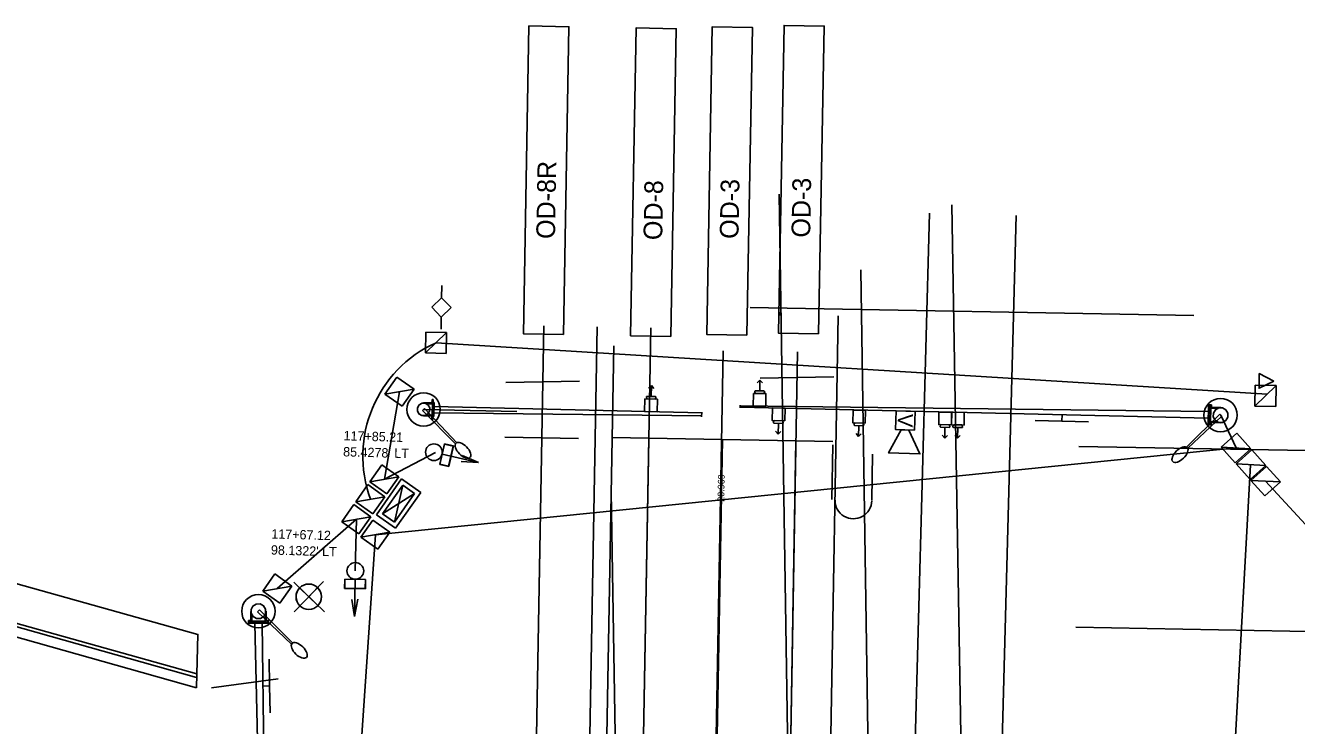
# Model space of a CAD drawing. Extents: x 925524 to 926006, y 853415 to 857998.
# Drawn here: x 925686 to 925876.1, y 853632 to 853736.7 of the extents above; entities that cross this region are included whole.
import ezdxf

# ---------------------------------------------------------------- set-up
doc = ezdxf.new("R2010")
doc.units = 0
for name, color, linetype in [('ConduitDB', 7, 'Continuous'), ('ConduitOT', 7, 'Continuous'), ('ConstLines', 7, 'Continuous'), ('ControllerB', 7, 'Continuous'), ('Core', 7, 'Continuous'), ('DetectorVeh', 7, 'Continuous'), ('EasePerpLine', 7, 'Continuous'), ('Luminaire', 7, 'Continuous'), ('Miscellaneous0', 7, 'Continuous'), ('NonPlottingEle_dp', 7, 'Continuous'), ('OverheadStr', 7, 'Continuous'), ('Pedestal', 7, 'Continuous'), ('PedHead', 7, 'Continuous'), ('PoleFound', 7, 'Continuous'), ('PullBox', 7, 'Continuous'), ('ScratchEle2_dp', 7, 'Continuous'), ('ScratchEle_dp', 7, 'Continuous'), ('SidewalkBack', 7, 'Continuous'), ('SignalHead', 7, 'Continuous'), ('SignPanel', 7, 'Continuous'), ('TextMinor', 7, 'Continuous'), ('TransformerAer', 7, 'Continuous')]:
    doc.layers.add(name, color=color, linetype=linetype)

msp = doc.modelspace()

# ---------------------------------------------------------------- linework, layer by layer
at = {"layer": 'ConduitDB'}
for p, q in [((925747.41, 853689.24), (925871.68, 853681.57)), ((925738.35, 853660.55), (925867.01, 853673.51)), ((925869.15, 853671.01), (925859.35, 853493.47)), ((925738.35, 853660.55), (925727.58, 853500.34))]:
    msp.add_line(p, q, dxfattribs=at)
at = {"layer": 'ConduitOT'}
for p, q in [((925739.7, 853668.83), (925741.95, 853681.92)), ((925739.7, 853668.83), (925747.31, 853672.84)), ((925871.43, 853668.55), (925884.05, 853654.81)), ((925723.67, 853652.5), (925735.5, 853662.86)), ((925735.5, 853662.86), (925735.35, 853655.13))]:
    msp.add_line(p, q, dxfattribs=at)
msp.add_lwpolyline([(925867.01, 853673.51), (925864.75, 853678.42)], dxfattribs=at)
msp.add_arc((925755.1, 853672.27), 18.63, 114.3621, 200.1371, dxfattribs=at)
at = {"layer": 'ConstLines'}
for p, q in [((925821.17, 853708.61), (925814.44, 853457.33)), ((925834.16, 853708.27), (925827.43, 853456.98)), ((925807.55, 853693.24), (925803.33, 853457.33)), ((925773.58, 853666.98), (925777.16, 853456.64))]:
    msp.add_line(p, q, dxfattribs=at)
at = {"layer": 'ControllerB'}
for p, q in [((925738.5, 853663.51), (925742.27, 853668.88)), ((925739.41, 853663.67), (925742.43, 853667.96)), ((925741.2, 853662.41), (925742.43, 853667.96)), ((925742.27, 853668.88), (925745.14, 853666.86)), ((925742.43, 853667.96), (925744.22, 853666.7)), ((925744.22, 853666.7), (925739.41, 853663.67)), ((925744.22, 853666.7), (925741.2, 853662.41)), ((925745.14, 853666.86), (925741.36, 853661.5)), ((925741.2, 853662.41), (925739.41, 853663.67)), ((925741.36, 853661.5), (925738.5, 853663.51))]:
    msp.add_line(p, q, dxfattribs=at)
at = {"layer": 'Core'}
for p, q in [((925726.14, 853653.44), (925730.73, 853649.01)), ((925726.22, 853649.03), (925730.6, 853653.56))]:
    msp.add_line(p, q, dxfattribs=at)
for points in [[(925727.02, 853652.59), (925728.39, 853651.27), (925727.06, 853649.9)], [(925729.71, 853652.64), (925728.39, 853651.27), (925729.76, 853649.95)]]:
    msp.add_lwpolyline(points, dxfattribs=at)
msp.add_circle((925728.39, 853651.27), 1.9, dxfattribs=at)
for start, end in [(135.9741, 225.9741), (315.9741, 45.9741)]:
    msp.add_arc((925728.39, 853651.27), 1.9, start, end, dxfattribs=at)
at = {"layer": 'DetectorVeh'}
msp.add_line((925816.94, 853676.22), (925818.11, 853676.18), dxfattribs=at)
msp.add_lwpolyline([(925818.93, 853676.16), (925819.02, 853678.97), (925816.21, 853679.06), (925816.12, 853676.25)], close=True, dxfattribs=at)
msp.add_lwpolyline([(925818.11, 853676.18), (925819.75, 853672.61), (925815.06, 853672.77), (925816.94, 853676.22)], dxfattribs=at)
at = {"layer": 'Luminaire'}
for p, q in [((925745.7, 853679.41), (925745.4, 853679.13)), ((925750.33, 853674.13), (925745.4, 853679.13)), ((925750.51, 853674.3), (925745.7, 853679.41)), ((925859.61, 853673.64), (925864.61, 853678.57)), ((925859.78, 853673.46), (925864.89, 853678.27)), ((925864.61, 853678.57), (925864.89, 853678.27)), ((925721, 853649.3), (925720.71, 853649)), ((925725.82, 853644.18), (925720.71, 853649)), ((925725.99, 853644.36), (925721, 853649.3))]:
    msp.add_line(p, q, dxfattribs=at)
for centre, major_axis in [((925751.45, 853673.15), (1.04, -1.08)), ((925858.63, 853672.52), (-1.08, -1.04)), ((925726.97, 853643.25), (1.08, -1.04))]:
    msp.add_ellipse(centre, major_axis=major_axis, ratio=0.5, dxfattribs=at)
at = {"layer": 'Miscellaneous0'}
for p, q in [((925661.93, 853659.63), (925711.79, 853645.62)), ((925662.19, 853653.12), (925711.63, 853639.23)), ((925662.27, 853653.61), (925711.64, 853639.75)), ((925661.96, 853651.62), (925711.59, 853637.68))]:
    msp.add_line(p, q, dxfattribs=at)
at = {"layer": 'NonPlottingEle_dp'}
for p, q in [((925768.72, 853674.91), (925757.72, 853675.11)), ((925773.72, 853675.05), (925784.72, 853674.85)), ((925763.22, 853675.01), (925759.78, 853483.16)), ((925779.22, 853674.95), (925775.92, 853490.92)), ((925784.72, 853674.85), (925795.72, 853674.66)), ((925790.22, 853674.76), (925786.81, 853484.28)), ((925795.72, 853674.66), (925806.72, 853674.46)), ((925801.22, 853674.56), (925797.82, 853484.67)), ((925806.71, 853674), (925806.56, 853665.83)), ((925928.9, 853672.19), (925843.53, 853673.72)), ((925812.68, 853672.56), (925812.56, 853665.73)), ((925928.42, 853645.19), (925843.05, 853646.72))]:
    msp.add_line(p, q, dxfattribs=at)
msp.add_arc((925809.81, 853665.68), 2.75, 178.9741, 358.9741, dxfattribs=at)
at = {"layer": 'OverheadStr'}
for p, q in [((925746.81, 853680.08), (925746.82, 853680.75)), ((925746.82, 853680.75), (925746.99, 853680.74)), ((925746.94, 853677.75), (925746.99, 853680.74)), ((925745.56, 853680.25), (925746.81, 853680.23)), ((925745.56, 853680.25), (925745.56, 853680.19)), ((925745.56, 853680.19), (925746.81, 853680.16)), ((925745.95, 853680.1), (925746.89, 853680.08)), ((925746.86, 853678.41), (925746.89, 853680.08)), ((925746.94, 853678.2), (925746.98, 853680.29)), ((925746.98, 853680.29), (925747.15, 853680.28)), ((925747.11, 853678.2), (925747.15, 853680.28)), ((925747.14, 853679.7), (925787.13, 853678.75)), ((925787.13, 853678.88), (925787.12, 853678.18)), ((925792.89, 853679.49), (925792.9, 853679.92)), ((925862.89, 853678.95), (925792.89, 853679.8)), ((925862.87, 853677.95), (925792.89, 853679.62)), ((925862.91, 853679.95), (925862.86, 853676.95)), ((925863.14, 853679.95), (925862.91, 853679.95)), ((925863.14, 853679.95), (925863.08, 853676.95)), ((925863.14, 853679.95), (925863.08, 853676.95)), ((925863.35, 853679.95), (925863.14, 853679.95)), ((925863.23, 853679.45), (925863.2, 853677.45)), ((925864.28, 853679.43), (925863.23, 853679.45)), ((925863.35, 853679.95), (925863.34, 853679.45)), ((925864.71, 853679.57), (925863.34, 853679.59)), ((925864.71, 853679.5), (925863.34, 853679.53)), ((925864.71, 853679.57), (925864.71, 853679.5)), ((925745.53, 853678.35), (925746.78, 853678.33)), ((925745.53, 853678.29), (925745.53, 853678.35)), ((925745.53, 853678.29), (925746.78, 853678.27)), ((925745.92, 853678.43), (925746.86, 853678.41)), ((925746.77, 853677.75), (925746.78, 853678.41)), ((925746.77, 853677.75), (925746.94, 853677.75)), ((925746.94, 853678.2), (925747.11, 853678.2)), ((925747.12, 853678.78), (925787.12, 853678.3)), ((925863.08, 853676.95), (925862.86, 853676.95)), ((925863.29, 853676.95), (925863.08, 853676.95)), ((925864.24, 853677.43), (925863.2, 853677.45)), ((925863.3, 853677.45), (925863.29, 853676.95)), ((925864.67, 853677.34), (925863.3, 853677.36)), ((925864.67, 853677.28), (925863.3, 853677.3)), ((925864.67, 853677.28), (925864.67, 853677.34)), ((925719.71, 853649.09), (925719.74, 853647.72)), ((925719.71, 853649.09), (925719.78, 853649.09)), ((925719.78, 853649.09), (925719.8, 853647.72)), ((925719.87, 853648.66), (925719.88, 853647.61)), ((925721.87, 853648.69), (925721.88, 853647.65)), ((925721.94, 853649.13), (925721.97, 853647.75)), ((925722.01, 853649.13), (925721.94, 853649.13)), ((925722.01, 853649.13), (925722.03, 853647.75)), ((925719.38, 853647.71), (925719.88, 853647.72)), ((925719.38, 853647.71), (925719.39, 853647.5)), ((925719.39, 853647.5), (925722.39, 853647.55)), ((925719.39, 853647.5), (925722.39, 853647.55)), ((925719.39, 853647.5), (925719.39, 853647.27)), ((925719.39, 853647.27), (925722.39, 853647.32)), ((925719.88, 853647.61), (925721.88, 853647.65)), ((925720.35, 853647.29), (925722.13, 853569.31)), ((925721.43, 853647.31), (925722.3, 853569.31)), ((925721.88, 853647.75), (925722.38, 853647.76)), ((925722.38, 853647.76), (925722.39, 853647.55)), ((925722.39, 853647.55), (925722.39, 853647.32))]:
    msp.add_line(p, q, dxfattribs=at)
for points in [[(925746.47, 853679.5), (925746.46, 853679.01), (925746.21, 853678.59), (925745.78, 853678.35), (925745.28, 853678.36), (925744.86, 853678.61), (925744.63, 853679.04), (925744.63, 853679.53), (925744.89, 853679.95), (925745.32, 853680.19), (925745.81, 853680.18), (925746.23, 853679.93)], [(925863.62, 853678.73), (925863.61, 853678.15), (925863.89, 853677.64), (925864.38, 853677.34), (925864.97, 853677.33), (925865.47, 853677.61), (925865.77, 853678.11), (925865.78, 853678.69), (925865.5, 853679.2), (925865, 853679.5), (925864.42, 853679.51), (925863.92, 853679.23)], [(925720.59, 853648.02), (925721.17, 853648.03), (925721.67, 853648.33), (925721.95, 853648.84), (925721.94, 853649.42), (925721.64, 853649.92), (925721.13, 853650.2), (925720.55, 853650.19), (925720.05, 853649.89), (925719.77, 853649.38), (925719.78, 853648.8), (925720.08, 853648.3)]]:
    msp.add_lwpolyline(points, close=True, dxfattribs=at)
at = {"layer": 'Pedestal'}
for p, q in [((925748.24, 853695.97), (925746.77, 853694.55)), ((925748.24, 853695.97), (925748.28, 853697.8)), ((925749.67, 853694.5), (925748.24, 853695.97)), ((925746.77, 853694.55), (925748.19, 853693.08)), ((925748.19, 853693.08), (925749.67, 853694.5)), ((925748.16, 853691.25), (925748.19, 853693.08))]:
    msp.add_line(p, q, dxfattribs=at)
at = {"layer": 'PedHead'}
for p, q in [((925748.67, 853674.11), (925747.98, 853671.06)), ((925747.98, 853671.1), (925748.66, 853674.07)), ((925748.66, 853674.07), (925749.97, 853673.78)), ((925750.01, 853673.81), (925748.67, 853674.11)), ((925749.97, 853673.78), (925749.29, 853670.8)), ((925749.32, 853670.76), (925750.01, 853673.81)), ((925748.32, 853672.59), (925753.76, 853671.35)), ((925753.76, 853671.35), (925751.19, 853671.48)), ((925753.76, 853671.35), (925751.32, 853672.37)), ((925749.29, 853670.8), (925747.98, 853671.1)), ((925747.98, 853671.06), (925749.32, 853670.76)), ((925733.76, 853653.91), (925733.74, 853652.53)), ((925733.74, 853652.53), (925736.86, 853652.48)), ((925736.89, 853653.85), (925733.76, 853653.91)), ((925733.78, 853652.57), (925733.8, 853653.91)), ((925736.83, 853652.51), (925733.78, 853652.57)), ((925733.8, 853653.91), (925736.85, 853653.85)), ((925735.33, 853653.88), (925735.23, 853648.31)), ((925736.85, 853653.85), (925736.83, 853652.51)), ((925736.86, 853652.48), (925736.89, 853653.85)), ((925735.23, 853648.31), (925734.83, 853650.85)), ((925735.23, 853648.31), (925735.73, 853650.9))]:
    msp.add_line(p, q, dxfattribs=at)
for centre in [(925747.1, 853672.87), (925735.35, 853655.13)]:
    msp.add_circle(centre, 1.25, dxfattribs=at)
at = {"layer": 'PoleFound'}
for centre in [(925745.55, 853679.27), (925864.69, 853678.42), (925720.86, 853649.11)]:
    msp.add_circle(centre, 2.5, dxfattribs=at)
at = {"layer": 'PullBox'}
for p, q in [((925745.82, 853687.71), (925745.88, 853690.83)), ((925745.82, 853687.71), (925749, 853690.77)), ((925745.88, 853690.83), (925749, 853690.77)), ((925749, 853690.77), (925748.94, 853687.65)), ((925748.94, 853687.65), (925745.82, 853687.71)), ((925739.77, 853681.54), (925741.57, 853684.09)), ((925741.57, 853684.09), (925744.13, 853682.29)), ((925869.81, 853679.77), (925869.87, 853682.9)), ((925869.81, 853679.77), (925872.99, 853682.84)), ((925869.87, 853682.9), (925872.99, 853682.84)), ((925872.99, 853682.84), (925872.94, 853679.72)), ((925739.77, 853681.54), (925744.13, 853682.29)), ((925742.33, 853679.74), (925739.77, 853681.54)), ((925744.13, 853682.29), (925742.33, 853679.74)), ((925872.94, 853679.72), (925869.81, 853679.77)), ((925864.8, 853673.63), (925867.13, 853675.72)), ((925867.13, 853675.72), (925869.21, 853673.39)), ((925866.89, 853671.3), (925864.8, 853673.63)), ((925864.8, 853673.63), (925869.21, 853673.39)), ((925869.21, 853673.39), (925866.89, 853671.3)), ((925867.04, 853671.12), (925869.37, 853673.21)), ((925869.37, 853673.21), (925871.45, 853670.88)), ((925737.52, 853668.45), (925739.32, 853671.01)), ((925739.32, 853671.01), (925741.87, 853669.21)), ((925869.12, 853668.79), (925867.04, 853671.12)), ((925867.04, 853671.12), (925871.45, 853670.88)), ((925871.45, 853670.88), (925869.12, 853668.79)), ((925869.23, 853668.67), (925871.56, 853670.76)), ((925871.56, 853670.76), (925873.64, 853668.43)), ((925735.43, 853665.47), (925737.22, 853668.03)), ((925737.22, 853668.03), (925739.78, 853666.23)), ((925737.52, 853668.45), (925741.87, 853669.21)), ((925740.07, 853666.65), (925737.52, 853668.45)), ((925741.87, 853669.21), (925740.07, 853666.65)), ((925871.31, 853666.34), (925869.23, 853668.67)), ((925869.23, 853668.67), (925873.64, 853668.43)), ((925873.64, 853668.43), (925871.31, 853666.34)), ((925735.43, 853665.47), (925739.78, 853666.23)), ((925739.78, 853666.23), (925737.98, 853663.68)), ((925733.32, 853662.48), (925735.12, 853665.04)), ((925735.12, 853665.04), (925737.67, 853663.24)), ((925737.98, 853663.68), (925735.43, 853665.47)), ((925733.32, 853662.48), (925737.67, 853663.24)), ((925735.88, 853660.68), (925733.32, 853662.48)), ((925737.67, 853663.24), (925735.88, 853660.68)), ((925736.17, 853660.17), (925737.97, 853662.73)), ((925737.97, 853662.73), (925740.53, 853660.93)), ((925736.17, 853660.17), (925740.53, 853660.93)), ((925738.73, 853658.38), (925736.17, 853660.17)), ((925740.53, 853660.93), (925738.73, 853658.38)), ((925721.5, 853652.12), (925723.3, 853654.68)), ((925723.3, 853654.68), (925725.85, 853652.88)), ((925721.5, 853652.12), (925725.85, 853652.88)), ((925725.85, 853652.88), (925724.05, 853650.32)), ((925724.05, 853650.32), (925721.5, 853652.12))]:
    msp.add_line(p, q, dxfattribs=at)
at = {"layer": 'ScratchEle2_dp'}
for p, q in [((925798.69, 853711.44), (925803.07, 853432.2)), ((925829.04, 853446.57), (925824.52, 853709.82)), ((925815.37, 853415.34), (925810.9, 853700.12)), ((925763.52, 853691.77), (925759.97, 853493.66)), ((925771.52, 853691.62), (925767.97, 853493.51)), ((925779.52, 853691.48), (925775.97, 853493.37)), ((925773.97, 853688.76), (925770.55, 853498.1)), ((925790.32, 853688.01), (925786.74, 853488.27)), ((925801.46, 853687.88), (925797.66, 853476.1)), ((925757.87, 853683.31), (925768.87, 853683.49)), ((925806.89, 853684.14), (925795.88, 853683.95)), ((925745.55, 853679.27), (925759.51, 853678.94)), ((925713.85, 853637.68), (925723.82, 853639.03))]:
    msp.add_line(p, q, dxfattribs=at)
at = {"layer": 'ScratchEle_dp'}
for p, q in [((925794.37, 853694.48), (925860.69, 853693.3)), ((925798.93, 853693.32), (925798.95, 853694.4))]:
    msp.add_line(p, q, dxfattribs=at)
at = {"layer": 'SidewalkBack'}
msp.add_line((925711.59, 853637.68), (925711.81, 853645.68), dxfattribs=at)
at = {"layer": 'SignalHead'}
for p, q in [((925779.2, 853682.43), (925779.6, 853682.82)), ((925779.57, 853681.21), (925779.6, 853682.82)), ((925779.99, 853682.41), (925779.6, 853682.82)), ((925795.43, 853683.25), (925795.83, 853683.64)), ((925795.8, 853682.04), (925795.83, 853683.64)), ((925796.22, 853683.24), (925795.83, 853683.64)), ((925780.19, 853681.2), (925778.96, 853681.22)), ((925796.42, 853682.03), (925795.19, 853682.05)), ((925797.98, 853677.21), (925799.2, 853677.18)), ((925798.59, 853677.2), (925798.55, 853675.59)), ((925798.16, 853676), (925798.55, 853675.59)), ((925798.96, 853675.98), (925798.55, 853675.59)), ((925810.01, 853676.87), (925811.24, 853676.84)), ((925810.2, 853675.65), (925810.59, 853675.24)), ((925810.63, 853676.85), (925810.59, 853675.24)), ((925810.99, 853675.63), (925810.59, 853675.24)), ((925822.89, 853676.61), (925824.12, 853676.59)), ((925823.08, 853675.4), (925823.47, 853674.99)), ((925823.5, 853676.6), (925823.47, 853674.99)), ((925823.88, 853675.38), (925823.47, 853674.99)), ((925824.79, 853676.58), (925826.02, 853676.55)), ((925824.99, 853675.36), (925825.38, 853674.96)), ((925825.41, 853676.56), (925825.38, 853674.96)), ((925825.79, 853675.35), (925825.38, 853674.96))]:
    msp.add_line(p, q, dxfattribs=at)
for points in [[(925778.63, 853680.83), (925780.5, 853680.8), (925780.47, 853678.92), (925778.59, 853678.96)], [(925794.86, 853681.66), (925796.73, 853681.63), (925796.7, 853679.75), (925794.83, 853679.78)], [(925799.54, 853677.56), (925797.66, 853677.62), (925797.71, 853679.49), (925799.59, 853679.44)], [(925811.58, 853677.22), (925809.7, 853677.27), (925809.75, 853679.15), (925811.63, 853679.1)], [(925824.45, 853676.98), (925822.57, 853677.01), (925822.6, 853678.88), (925824.48, 853678.85)], [(925826.35, 853676.94), (925824.48, 853676.98), (925824.51, 853678.85), (925826.39, 853678.82)]]:
    msp.add_lwpolyline(points, close=True, dxfattribs=at)
for points in [[(925778.95, 853680.83), (925780.18, 853680.8)], [(925795.18, 853681.65), (925796.41, 853681.63)], [(925799.21, 853677.57), (925797.99, 853677.61)], [(925811.25, 853677.23), (925810.03, 853677.26)], [(925824.12, 853676.98), (925822.89, 853677)], [(925826.03, 853676.95), (925824.8, 853676.97)]]:
    msp.add_lwpolyline(points, dxfattribs=at)
for centre, radius, start, end in [((925778.96, 853681.1), 0.121, 88.9741, 208.2939), ((925776.87, 853679.98), 2.25, 22.1907, 28.2939), ((925782.23, 853679.88), 2.25, 149.6543, 155.7575), ((925780.18, 853681.08), 0.121, 329.6543, 88.9741), ((925795.19, 853681.93), 0.121, 88.9741, 208.2939), ((925793.1, 853680.8), 2.25, 22.1907, 28.2939), ((925798.46, 853680.71), 2.25, 149.6543, 155.7575), ((925796.42, 853681.9), 0.121, 329.6543, 88.9741), ((925797.98, 853677.33), 0.121, 149.1461, 268.4659), ((925795.94, 853678.55), 2.25, 329.1461, 335.2494), ((925799.21, 853677.3), 0.121, 268.466, 27.7857), ((925801.3, 853678.4), 2.25, 201.6825, 207.7858), ((925810.02, 853676.99), 0.121, 149.1461, 268.4659), ((925807.98, 853678.2), 2.25, 329.1461, 335.2494), ((925811.25, 853676.96), 0.121, 268.466, 27.7857), ((925813.34, 853678.06), 2.25, 201.6825, 207.7858), ((925820.84, 853677.93), 2.25, 329.6543, 335.7575), ((925826.2, 853677.83), 2.25, 202.1907, 208.2939), ((925822.75, 853677.89), 2.25, 329.6543, 335.7575), ((925828.11, 853677.8), 2.25, 202.1907, 208.2939), ((925822.89, 853676.73), 0.121, 149.6543, 268.9741), ((925824.12, 853676.71), 0.121, 268.9741, 28.2939), ((925824.8, 853676.7), 0.121, 149.6543, 268.9741), ((925826.03, 853676.67), 0.121, 268.9741, 28.2939)]:
    msp.add_arc(centre, radius, start, end, dxfattribs=at)
at = {"layer": 'SignPanel'}
for p, q in [((925840.97, 853677.51), (925836.98, 853677.6)), ((925840.97, 853677.51), (925841, 853678.51)), ((925840.97, 853677.51), (925844.97, 853677.41)), ((925722.54, 853637.94), (925722.47, 853641.94)), ((925722.54, 853637.94), (925721.54, 853637.92)), ((925722.54, 853637.94), (925722.6, 853633.94))]:
    msp.add_line(p, q, dxfattribs=at)
at = {"layer": 'TextMinor'}
for points in [[(925766.46, 853690.47), (925760.47, 853690.57), (925761.29, 853736.57), (925767.29, 853736.46), (925766.46, 853690.47)], [(925782.49, 853690.18), (925776.49, 853690.29), (925777.32, 853736.28), (925783.32, 853736.17), (925782.49, 853690.18)], [(925793.89, 853690.37), (925787.89, 853690.48), (925788.71, 853736.47), (925794.71, 853736.37), (925793.89, 853690.37)], [(925804.61, 853690.55), (925798.62, 853690.66), (925799.44, 853736.65), (925805.44, 853736.55), (925804.61, 853690.55)]]:
    msp.add_lwpolyline(points, dxfattribs=at)
at = {"layer": 'TransformerAer'}
msp.add_lwpolyline([(925872.66, 853683.49), (925870.45, 853682.43), (925870.49, 853684.62)], close=True, dxfattribs=at)

# ---------------------------------------------------------------- texts
at = {"layer": 'DetectorVeh'}
msp.add_text('V', height=2.25, rotation=268.1218, dxfattribs=at).set_placement((925816.48, 853678.65))
at = {"layer": 'EasePerpLine'}
msp.add_text('20.969', height=1, rotation=88.973, dxfattribs=at).set_placement((925790.49, 853665.47))
at = {"layer": 'NonPlottingEle_dp'}
for s, p in [('117+85.21', (925733.58, 853674.66)), ("85.4278' LT", (925733.51, 853672.26)), ('117+67.12', (925722.78, 853659.98)), ("98.1322' LT", (925722.72, 853657.58))]:
    msp.add_text(s, height=1.4, rotation=358.3939, dxfattribs=at).set_placement(p)
at = {"layer": 'TextMinor'}
for s, p in [('OD-8R', (925765.19, 853704.73)), ('OD-8', (925781.22, 853704.55)), ('OD-3', (925792.62, 853704.74)), ('OD-3', (925803.34, 853704.93))]:
    msp.add_text(s, height=2.8, rotation=88.9741, dxfattribs=at).set_placement(p)

doc.saveas('drawing.dxf')
